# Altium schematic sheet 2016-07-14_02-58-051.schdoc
size 309 x 119 mm; SheetNumber: 1; SheetTotal: 1
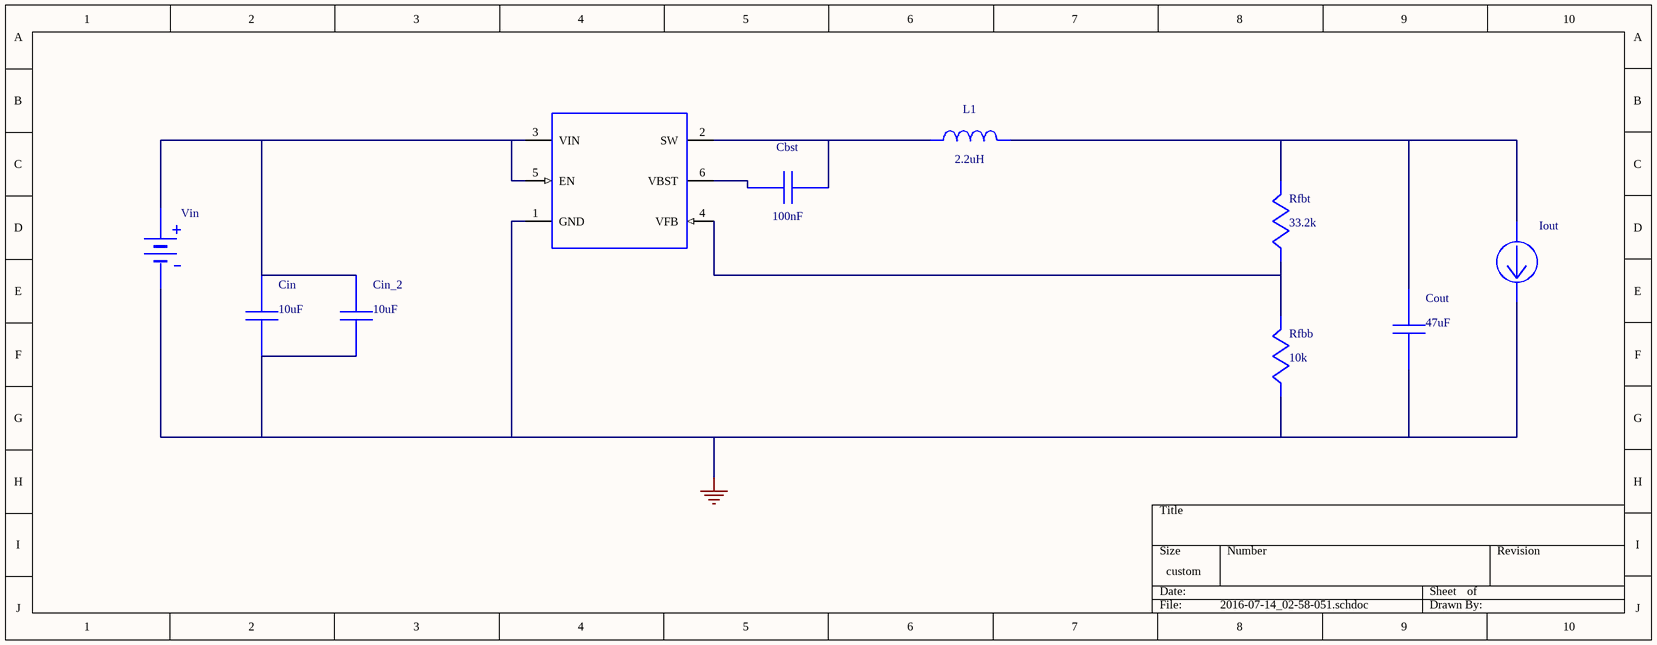
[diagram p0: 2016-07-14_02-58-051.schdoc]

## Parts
Cbst  value 100nF  (hidden comment: 08053C104KAT2A)
Cin  value 10uF  (hidden comment: GRM21BR61C106KE15L)
Cin_2  value 10uF  (hidden comment: GRM21BR61C106KE15L)
Cout  value 47uF  (hidden comment: C3216JB1A476M)
Iout  WB_CURRENT_LOAD  (value not drawn)
L1  value 2.2uH  (hidden comment: SRN8040-2R2Y)
Rfbb  value 10k  (hidden comment: CRCW040210K0FKED)
Rfbt  value 33.2k  (hidden comment: CRCW040233K2FKED)
U1  TPS563209DDCR  (value not drawn)
Vin  WB_BATTERY  (value not drawn)

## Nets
0: Cin.2 Cin_2.2 Cout.2 Iout.2(-) Rfbb.2 U1.1(GND) Vin.2(-)
NetCbst_1: Cbst.1 L1.1 U1.2(SW)
NetCbst_2: Cbst.2 U1.6(VBST)
NetCin_1: Cin.1 Cin_2.1 U1.3(VIN) U1.5(EN) Vin.1(+)
NetCout_1: Cout.1 Iout.1(+) L1.2 Rfbt.1
NetRfbb_1: Rfbb.1 Rfbt.2 U1.4(VFB)

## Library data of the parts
Cbst = 08053C104KAT2A: Manufacturer Name: AVX
Cin Cin_2 = GRM21BR61C106KE15L: GRM21BR61C106KE1; Manufacturer Name: MuRata
Cout = C3216JB1A476M: Manufacturer Name: TDK
L1 = SRN8040-2R2Y: Manufacturer Name: Bourns
Rfbb = CRCW040210K0FKED: Manufacturer Name: Vishay-Dale
Rfbt = CRCW040233K2FKED: Manufacturer Name: Vishay-Dale
U1 = TPS563209DDCR: Manufacturer Name: Texas Instruments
